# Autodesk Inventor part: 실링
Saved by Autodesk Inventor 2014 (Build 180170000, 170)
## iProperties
Created: 2026-03
Part Number: 실링
Material: 고무
Document SubType Name: Modeling
Designer: dg
Density: 0.93 g/cm^3
Appearance: 고무 - 검은색 - 버전 1.1
Mass: 0.0412249 g
Surface Area: 1.40806 cm^2
Volume: 0.0443279 cm^3
Author: jhkim
Creation Date: 2025-06-27
Sending System: Autodesk Inventor 2026
Preprocessor: ST-DEVELOPER v20.1
Author: dg
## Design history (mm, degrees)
node "실링1"
node "솔리드1"
node "기준1"
